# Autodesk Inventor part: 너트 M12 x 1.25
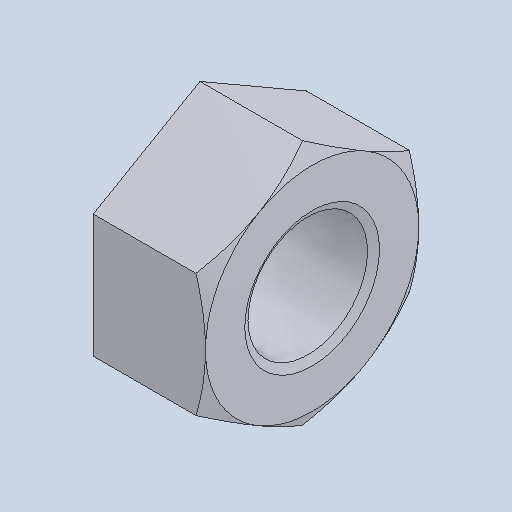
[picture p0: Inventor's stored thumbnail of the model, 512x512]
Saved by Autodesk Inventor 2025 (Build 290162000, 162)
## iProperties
Created: 2024-08
Part Number: 너트 M12 x 1.25
Material: 스테인리스강
Description: 6각 너트
Document SubType Name: Modeling
Designer: Administrator
Density: 8.08 g/cm^3
Appearance: 기본값
Author: jhkim
Sending System: Autodesk Inventor 2025
Preprocessor: ST-DEVELOPER v20
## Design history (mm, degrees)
feature "Solid1"
node "솔리드1"
